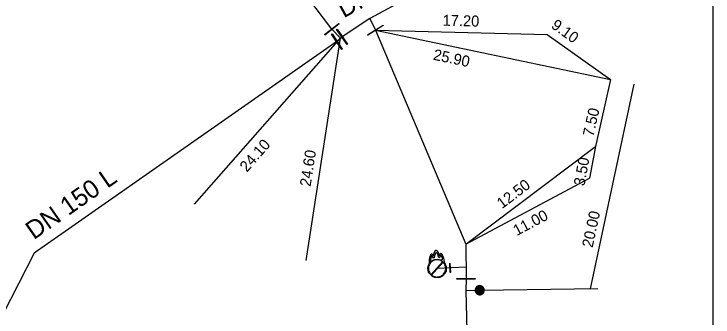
# Model space of a CAD drawing. Extents: x -820257 to -819974, y -1070894 to -1070484.
# Drawn here: x -820052 to -819975.6, y -1070665.6 to -1070632.5 of the extents above; entities that cross this region are included whole.
import ezdxf

# ---------------------------------------------------------------- set-up
doc = ezdxf.new("R2010")
doc.units = 0
for name, color, linetype in [('Default', 7, 'Continuous'), ('Hyd-odbočka', 7, 'Continuous'), ('Hyd-šoupě', 7, 'Continuous'), ('Hydrant', 7, 'Continuous'), ('Oměrka vodovodu', 7, 'Continuous'), ('Oměrka-text', 7, 'Continuous'), ('Přípojka vodovodu', 7, 'Continuous'), ('Přípojkový uzávěr', 7, 'Continuous'), ('Roz-řad', 7, 'Continuous'), ('Roz-řad-popis základní', 7, 'Continuous'), ('Řad-šoupě', 7, 'Continuous')]:
    doc.layers.add(name, color=color, linetype=linetype)

msp = doc.modelspace()

# ---------------------------------------------------------------- linework, layer by layer
at = {"layer": 'Default'}
msp.add_line((-819975.603, -1070893.932), (-819975.603, -1070484.403), dxfattribs=at)
at = {"layer": 'Hyd-odbočka'}
msp.add_line((-820002.621, -1070660.177), (-820005.774, -1070660.329), dxfattribs=at)
at = {"layer": 'Hyd-šoupě'}
msp.add_lwpolyline([(-820004.369, -1070659.761), (-820004.321, -1070660.76), (-820004.352, -1070660.761), (-820004.4, -1070659.762), (-820004.369, -1070659.761)], dxfattribs=at)
at = {"layer": 'Hydrant'}
for points in [[(-820005.934, -1070658.335), (-820005.854, -1070658.33)], [(-820006.609, -1070659.497), (-820006.59, -1070659.294)], [(-820006.406, -1070658.745), (-820006.334, -1070658.741), (-820006.178, -1070658.987)], [(-820006.09, -1070659.188), (-820006.183, -1070659.193), (-820006.359, -1070658.936)], [(-820005.926, -1070659.34), (-820005.743, -1070659.329)], [(-820005.361, -1070658.876), (-820005.52, -1070659.153), (-820005.595, -1070659.158)], [(-820005.531, -1070658.947), (-820005.41, -1070658.685), (-820005.336, -1070658.68)], [(-820005.087, -1070659.206), (-820005.043, -1070659.406), (-820005.028, -1070659.529)], [(-820006.608, -1070659.773), (-820006.638, -1070659.804)], [(-820006.42, -1070661.012), (-820005.174, -1070659.606)], [(-820005.129, -1070659.646), (-820006.375, -1070661.054)]]:
    msp.add_lwpolyline(points, dxfattribs=at)
for points, degree in [([(-820006.178, -1070658.987), (-820006.127, -1070658.605), (-820005.934, -1070658.335)], 2), ([(-820005.854, -1070658.33), (-820005.63, -1070658.573), (-820005.531, -1070658.947)], 2), ([(-820006.59, -1070659.294), (-820006.558, -1070659.022), (-820006.406, -1070658.745)], 2), ([(-820006.359, -1070658.936), (-820006.555, -1070659.266), (-820006.471, -1070659.618)], 2), ([(-820006.471, -1070659.618), (-820006.205, -1070659.379), (-820005.926, -1070659.34)], 2), ([(-820005.595, -1070659.158), (-820005.645, -1070658.77), (-820005.885, -1070658.461), (-820006.056, -1070658.798), (-820006.09, -1070659.188)], 3), ([(-820005.743, -1070659.329), (-820005.461, -1070659.336), (-820005.166, -1070659.541), (-820005.13, -1070659.2), (-820005.361, -1070658.876)], 3), ([(-820005.336, -1070658.68), (-820005.154, -1070658.938), (-820005.087, -1070659.206)], 2), ([(-820005.011, -1070659.68), (-820004.797, -1070659.928), (-820004.776, -1070660.271), (-820004.751, -1070660.684), (-820005.026, -1070660.993), (-820005.301, -1070661.302), (-820005.716, -1070661.327), (-820006.128, -1070661.352), (-820006.438, -1070661.078), (-820006.748, -1070660.804), (-820006.773, -1070660.391), (-820006.793, -1070660.044), (-820006.608, -1070659.773)], 3), ([(-820005.174, -1070659.606), (-820005.261, -1070659.535), (-820005.363, -1070659.486), (-820005.595, -1070659.379), (-820005.831, -1070659.393), (-820006.067, -1070659.407), (-820006.284, -1070659.542), (-820006.501, -1070659.676), (-820006.613, -1070659.908), (-820006.725, -1070660.14), (-820006.71, -1070660.385), (-820006.696, -1070660.629), (-820006.557, -1070660.844), (-820006.499, -1070660.938), (-820006.42, -1070661.012)], 3), ([(-820006.638, -1070659.804), (-820006.623, -1070659.785), (-820006.609, -1070659.767), (-820006.61, -1070659.606), (-820006.609, -1070659.497)], 3), ([(-820006.375, -1070661.054), (-820006.292, -1070661.121), (-820006.192, -1070661.168), (-820005.962, -1070661.279), (-820005.718, -1070661.265), (-820005.474, -1070661.25), (-820005.259, -1070661.113), (-820005.043, -1070660.976), (-820004.933, -1070660.746), (-820004.824, -1070660.516), (-820004.839, -1070660.273), (-820004.853, -1070660.027), (-820004.994, -1070659.81), (-820005.054, -1070659.718), (-820005.129, -1070659.646)], 3), ([(-820005.028, -1070659.529), (-820005.025, -1070659.552), (-820005.011, -1070659.68)], 2)]:
    msp.add_open_spline(points, degree=degree, dxfattribs=at)
at = {"layer": 'Oměrka vodovodu'}
for p, q in [((-820012.528, -1070634.285), (-819993.735, -1070634.76)), ((-820012.528, -1070634.285), (-819986.81, -1070639.695)), ((-819993.735, -1070634.76), (-819986.81, -1070639.695)), ((-820032.32, -1070653.29), (-820016.356, -1070635.176)), ((-820020.11, -1070659.45), (-820016.356, -1070635.176)), ((-819988.986, -1070662.551), (-819984.214, -1070640.199)), ((-819986.81, -1070639.695), (-819988.462, -1070647.011)), ((-820002.632, -1070657.679), (-819988.462, -1070647.011)), ((-819988.462, -1070647.011), (-819989.098, -1070650.452)), ((-820002.632, -1070657.679), (-819989.098, -1070650.452))]:
    msp.add_line(p, q, dxfattribs=at)
at = {"layer": 'Přípojka vodovodu'}
msp.add_lwpolyline([(-820002.619, -1070662.727), (-820001.118, -1070662.708), (-819988.215, -1070662.541)], dxfattribs=at)
at = {"layer": 'Přípojkový uzávěr'}
for points in [[(-820001.125, -1070662.208), (-820000.999, -1070662.206), (-820000.879, -1070662.269), (-820000.759, -1070662.332), (-820000.689, -1070662.451), (-820000.62, -1070662.571), (-820000.619, -1070662.702), (-820000.617, -1070662.832), (-820000.681, -1070662.951), (-820000.746, -1070663.071), (-820000.864, -1070663.138), (-820000.982, -1070663.206), (-820001.113, -1070663.208), (-820001.242, -1070663.209), (-820001.362, -1070663.145), (-820001.482, -1070663.08), (-820001.549, -1070662.962), (-820001.617, -1070662.844), (-820001.618, -1070662.715), (-820001.62, -1070662.584), (-820001.555, -1070662.462), (-820001.489, -1070662.341), (-820001.37, -1070662.275), (-820001.252, -1070662.209), (-820001.125, -1070662.208)], [(-820001.125, -1070662.255), (-820001.239, -1070662.256), (-820001.347, -1070662.316), (-820001.454, -1070662.375), (-820001.514, -1070662.485), (-820001.573, -1070662.595), (-820001.572, -1070662.714), (-820001.57, -1070662.832), (-820001.509, -1070662.938), (-820001.448, -1070663.045), (-820001.339, -1070663.104), (-820001.23, -1070663.162), (-820001.113, -1070663.161), (-820000.995, -1070663.159), (-820000.888, -1070663.098), (-820000.78, -1070663.037), (-820000.722, -1070662.928), (-820000.664, -1070662.82), (-820000.665, -1070662.702), (-820000.667, -1070662.584), (-820000.73, -1070662.475), (-820000.793, -1070662.367), (-820000.902, -1070662.31), (-820001.011, -1070662.253), (-820001.125, -1070662.255)], [(-820001.124, -1070662.289), (-820001.018, -1070662.287), (-820000.918, -1070662.34), (-820000.817, -1070662.393), (-820000.759, -1070662.493), (-820000.701, -1070662.593), (-820000.7, -1070662.703), (-820000.698, -1070662.812), (-820000.752, -1070662.912), (-820000.805, -1070663.012), (-820000.905, -1070663.069), (-820001.004, -1070663.125), (-820001.114, -1070663.127), (-820001.222, -1070663.128), (-820001.323, -1070663.074), (-820001.424, -1070663.02), (-820001.48, -1070662.921), (-820001.536, -1070662.822), (-820001.537, -1070662.713), (-820001.539, -1070662.604), (-820001.484, -1070662.502), (-820001.429, -1070662.401), (-820001.329, -1070662.345), (-820001.23, -1070662.29), (-820001.124, -1070662.289)], [(-820001.124, -1070662.333), (-820001.281, -1070662.335), (-820001.388, -1070662.446), (-820001.495, -1070662.557), (-820001.493, -1070662.713), (-820001.491, -1070662.868), (-820001.38, -1070662.976), (-820001.269, -1070663.085), (-820001.115, -1070663.083), (-820000.958, -1070663.081), (-820000.85, -1070662.97), (-820000.742, -1070662.859), (-820000.744, -1070662.703), (-820000.746, -1070662.548), (-820000.856, -1070662.439), (-820000.967, -1070662.331), (-820001.124, -1070662.333)], [(-820001.124, -1070662.379), (-820000.987, -1070662.377), (-820000.89, -1070662.471), (-820000.793, -1070662.566), (-820000.791, -1070662.702), (-820000.79, -1070662.839), (-820000.884, -1070662.936), (-820000.979, -1070663.033), (-820001.115, -1070663.035), (-820001.252, -1070663.036), (-820001.349, -1070662.942), (-820001.446, -1070662.847), (-820001.448, -1070662.711), (-820001.449, -1070662.575), (-820001.355, -1070662.477), (-820001.26, -1070662.38), (-820001.124, -1070662.379)], [(-820001.123, -1070662.418), (-820001.243, -1070662.42), (-820001.326, -1070662.505), (-820001.41, -1070662.591), (-820001.408, -1070662.71), (-820001.406, -1070662.83), (-820001.321, -1070662.913), (-820001.236, -1070662.997), (-820001.116, -1070662.995), (-820000.996, -1070662.994), (-820000.913, -1070662.908), (-820000.829, -1070662.823), (-820000.831, -1070662.703), (-820000.832, -1070662.583), (-820000.918, -1070662.5), (-820001.003, -1070662.417), (-820001.123, -1070662.418)], [(-820001.122, -1070662.458), (-820001.017, -1070662.456), (-820000.944, -1070662.529), (-820000.87, -1070662.601), (-820000.868, -1070662.705), (-820000.867, -1070662.808), (-820000.939, -1070662.882), (-820001.012, -1070662.956), (-820001.116, -1070662.958), (-820001.219, -1070662.959), (-820001.293, -1070662.887), (-820001.367, -1070662.815), (-820001.368, -1070662.711), (-820001.37, -1070662.607), (-820001.298, -1070662.533), (-820001.227, -1070662.459), (-820001.122, -1070662.458)], [(-820001.122, -1070662.504), (-820001.206, -1070662.505), (-820001.265, -1070662.565), (-820001.323, -1070662.625), (-820001.322, -1070662.71), (-820001.321, -1070662.794), (-820001.261, -1070662.853), (-820001.201, -1070662.911), (-820001.116, -1070662.91), (-820001.032, -1070662.909), (-820000.974, -1070662.849), (-820000.915, -1070662.789), (-820000.916, -1070662.705), (-820000.917, -1070662.62), (-820000.977, -1070662.561), (-820001.037, -1070662.503), (-820001.122, -1070662.504)], [(-820001.121, -1070662.539), (-820001.051, -1070662.538), (-820001.001, -1070662.586), (-820000.951, -1070662.635), (-820000.951, -1070662.705), (-820000.95, -1070662.775), (-820000.998, -1070662.825), (-820001.047, -1070662.875), (-820001.117, -1070662.876), (-820001.187, -1070662.876), (-820001.237, -1070662.828), (-820001.287, -1070662.78), (-820001.287, -1070662.709), (-820001.288, -1070662.639), (-820001.24, -1070662.589), (-820001.191, -1070662.54), (-820001.121, -1070662.539)], [(-820001.121, -1070662.583), (-820001.172, -1070662.583), (-820001.208, -1070662.62), (-820001.244, -1070662.657), (-820001.243, -1070662.709), (-820001.243, -1070662.761), (-820001.206, -1070662.797), (-820001.169, -1070662.833), (-820001.117, -1070662.833), (-820001.065, -1070662.832), (-820001.029, -1070662.795), (-820000.993, -1070662.758), (-820000.993, -1070662.706), (-820000.994, -1070662.654), (-820001.031, -1070662.618), (-820001.068, -1070662.582), (-820001.121, -1070662.583)], [(-820001.12, -1070662.629), (-820001.087, -1070662.629), (-820001.064, -1070662.651), (-820001.041, -1070662.673), (-820001.041, -1070662.707), (-820001.04, -1070662.739), (-820001.063, -1070662.762), (-820001.085, -1070662.785), (-820001.118, -1070662.786), (-820001.15, -1070662.786), (-820001.173, -1070662.763), (-820001.197, -1070662.741), (-820001.197, -1070662.709), (-820001.198, -1070662.675), (-820001.175, -1070662.653), (-820001.152, -1070662.63), (-820001.12, -1070662.629)], [(-820001.12, -1070662.661), (-820001.139, -1070662.661), (-820001.153, -1070662.675), (-820001.166, -1070662.688), (-820001.166, -1070662.708), (-820001.166, -1070662.728), (-820001.152, -1070662.741), (-820001.138, -1070662.755), (-820001.118, -1070662.754), (-820001.098, -1070662.754), (-820001.085, -1070662.74), (-820001.072, -1070662.727), (-820001.072, -1070662.707), (-820001.072, -1070662.687), (-820001.086, -1070662.674), (-820001.1, -1070662.66), (-820001.12, -1070662.661)]]:
    msp.add_open_spline(points, degree=3, dxfattribs=at)
at = {"layer": 'Roz-řad'}
for p, q in [((-820017.29, -1070634.19), (-820022.07, -1070627.805)), ((-820013.124, -1070633.027), (-820016.17, -1070635)), ((-820013.124, -1070633.027), (-820012.528, -1070634.285)), ((-820016.356, -1070635.176), (-820017.29, -1070634.19)), ((-820016.74, -1070635.54), (-820016.356, -1070635.176)), ((-820016.356, -1070635.176), (-820016.17, -1070635))]:
    msp.add_line(p, q, dxfattribs=at)
for points in [[(-820004.782, -1070628.062), (-820005.144, -1070628.674), (-820013.124, -1070633.027)], [(-820012.528, -1070634.285), (-820002.632, -1070657.679), (-820002.616, -1070661.467)], [(-820016.74, -1070635.54), (-820049.836, -1070658.668), (-820053.253, -1070665.35)], [(-820002.616, -1070661.467), (-820002.619, -1070662.727), (-820001.798, -1070696.757), (-820001.582, -1070715.112)]]:
    msp.add_lwpolyline(points, dxfattribs=at)
at = {"layer": 'Řad-šoupě'}
for points in [[(-820018.107, -1070634.767), (-820016.511, -1070633.562), (-820016.473, -1070633.612), (-820018.07, -1070634.817), (-820018.107, -1070634.767)], [(-820011.66, -1070633.786), (-820013.363, -1070634.836), (-820013.396, -1070634.782), (-820011.693, -1070633.733), (-820011.66, -1070633.786)], [(-820016.212, -1070636.39), (-820017.319, -1070634.724), (-820017.267, -1070634.69), (-820016.16, -1070636.355), (-820016.212, -1070636.39)], [(-820016.717, -1070634.161), (-820015.572, -1070635.802), (-820015.624, -1070635.837), (-820016.768, -1070634.197), (-820016.717, -1070634.161)], [(-820003.616, -1070661.434), (-820001.616, -1070661.438), (-820001.616, -1070661.501), (-820003.616, -1070661.496), (-820003.616, -1070661.434)]]:
    msp.add_lwpolyline(points, dxfattribs=at)

# ---------------------------------------------------------------- texts
at = {"layer": 'Oměrka-text'}
for s, rotation, p in [('17.20', 358.55143, (-820005.189, -1070633.798)), (' 9.10', 324.52501, (-819993.754, -1070633.713)), ('25.90', 348.12005, (-820006.275, -1070637.508)), (' 7.50', 77.27562, (-819988.79, -1070646.426)), ('24.10', 48.61003, (-820026.583, -1070649.874)), ('24.60', 81.2088, (-820019.617, -1070651.446)), (' 3.50', 79.5282, (-819989.754, -1070651.821)), ('12.50', 36.97457, (-819998.678, -1070653.86)), ('11.00', 28.10169, (-819997.062, -1070656.801)), ('20.00', 77.94867, (-819988.774, -1070658.122))]:
    msp.add_text(s, height=1.2, rotation=rotation, dxfattribs=at).set_placement(p)
at = {"layer": 'Roz-řad-popis základní'}
for s, rotation, p in [('DN 200 L', 28.61013, (-820015.996, -1070633.003)), ('DN 150 L', 34.93152, (-820049.879, -1070657.252))]:
    msp.add_text(s, height=2, rotation=rotation, dxfattribs=at).set_placement(p)

doc.saveas('drawing.dxf')
